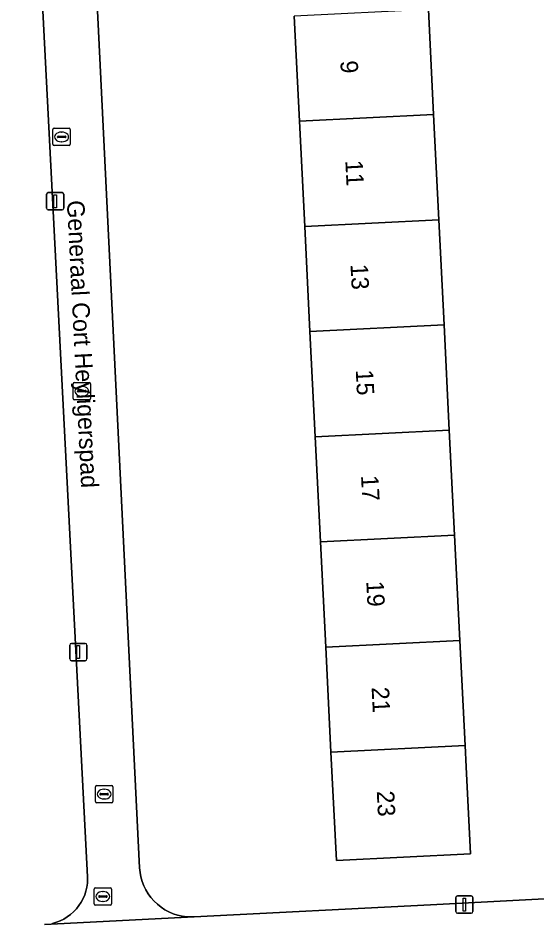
# Model space of a CAD drawing. Extents: x 161084 to 161928, y 385354 to 386522.
# Drawn here: x 161421.8 to 161451.7, y 385657.1 to 385709.2 of the extents above; entities that cross this region are included whole.
import ezdxf

# ---------------------------------------------------------------- set-up
doc = ezdxf.new("R2010")
doc.units = 0
for name, color, linetype in [('IMGEO_Erf', 7, 'Continuous'), ('IMGEO_Kolk', 7, 'Continuous'), ('IMGEO_Lichtmast', 7, 'Continuous'), ('IMGEO_Openbare_ruimte_label', 7, 'Continuous'), ('IMGEO_Pand', 7, 'Continuous'), ('IMGEO_Pand_nummerreeks', 7, 'Continuous'), ('IMGEO_Rioolput', 7, 'Continuous'), ('IMGEO_Voetpad_open', 7, 'Continuous')]:
    doc.layers.add(name, color=color, linetype=linetype)

msp = doc.modelspace()

# ---------------------------------------------------------------- linework, layer by layer
at = {"layer": 'IMGEO_Erf'}
for points in [[(161425.778, 385659.205), (161425.809, 385659.438), (161425.819, 385659.672), (161425.816, 385659.799), (161421.822, 385737.157)], [(161425.062, 385736.633), (161428.815, 385660.315), (161428.84, 385660.05), (161428.889, 385659.788), (161428.961, 385659.531), (161429.056, 385659.282), (161429.172, 385659.043), (161429.31, 385658.815), (161429.467, 385658.6), (161429.643, 385658.399), (161429.836, 385658.216), (161430.045, 385658.05), (161430.267, 385657.904), (161430.502, 385657.778), (161430.747, 385657.674), (161431.001, 385657.592), (161431.26, 385657.532), (161431.524, 385657.497), (161431.791, 385657.485), (161431.947, 385657.489), (161445.557, 385658.188), (161454.66, 385658.656)], [(161445.425, 385709.704), (161445.727, 385703.653), (161446.029, 385697.602), (161446.331, 385691.55), (161446.632, 385685.499), (161446.934, 385679.447), (161447.236, 385673.396), (161447.538, 385667.344), (161447.599, 385666.114), (161447.848, 385661.12), (161440.133, 385660.736), (161439.823, 385666.96), (161439.521, 385673.012), (161439.219, 385679.063), (161438.917, 385685.115), (161438.616, 385691.166), (161438.314, 385697.218), (161438.012, 385703.269), (161437.711, 385709.32)], [(161423.797, 385657.118), (161424.022, 385657.181), (161424.241, 385657.265), (161424.452, 385657.367), (161424.652, 385657.488), (161424.841, 385657.627), (161425.017, 385657.782), (161425.178, 385657.952), (161425.324, 385658.136), (161425.452, 385658.331), (161425.563, 385658.538), (161425.654, 385658.754), (161425.726, 385658.977), (161425.778, 385659.205)]]:
    msp.add_lwpolyline(points, dxfattribs=at)
at = {"layer": 'IMGEO_Kolk'}
for p, q in [((161425.06, 385688.232), (161425.912, 385688.232)), ((161424.985, 385687.306), (161424.985, 385688.158)), ((161425.244, 385687.726), (161425.244, 385687.738)), ((161425.682, 385687.689), (161425.284, 385687.689)), ((161425.287, 385687.775), (161425.685, 385687.775)), ((161425.473, 385688.012), (161425.498, 385688.012)), ((161425.728, 385687.738), (161425.728, 385687.726)), ((161425.986, 385688.158), (161425.986, 385687.306)), ((161425.912, 385687.232), (161425.06, 385687.232)), ((161425.496, 385687.452), (161425.471, 385687.452)), ((161426.271, 385664.126), (161426.271, 385664.978)), ((161426.346, 385665.052), (161427.198, 385665.052)), ((161426.759, 385664.832), (161426.784, 385664.832)), ((161427.272, 385664.978), (161427.272, 385664.126)), ((161426.53, 385664.546), (161426.53, 385664.558)), ((161426.968, 385664.509), (161426.57, 385664.509)), ((161426.573, 385664.595), (161426.971, 385664.595)), ((161426.782, 385664.272), (161426.757, 385664.272)), ((161427.014, 385664.558), (161427.014, 385664.546)), ((161427.198, 385664.052), (161426.346, 385664.052))]:
    msp.add_line(p, q, dxfattribs=at)
for points in [[(161425.06, 385688.232), (161425.912, 385688.232)], [(161424.985, 385687.306), (161424.985, 385688.158)], [(161425.986, 385688.158), (161425.986, 385687.306)], [(161425.912, 385687.232), (161425.06, 385687.232)], [(161426.271, 385664.126), (161426.271, 385664.978)], [(161426.346, 385665.052), (161427.198, 385665.052)], [(161427.272, 385664.978), (161427.272, 385664.126)], [(161427.198, 385664.052), (161426.346, 385664.052)]]:
    msp.add_lwpolyline(points, dxfattribs=at)
for centre, radius, start, end in [((161425.062, 385688.156), 0.0765, 91.552, 178.448), ((161425.062, 385688.156), 0.0765, 91.552, 178.448), ((161425.91, 385688.156), 0.0765, 1.552, 88.448), ((161425.91, 385688.156), 0.0765, 1.552, 88.448), ((161425.284, 385687.735), 0.0403, 85.8775, 175.7526), ((161425.281, 385687.725), 0.0366, 178.938, 274.7102), ((161425.685, 385687.732), 0.043, 264.8664, 352.4533), ((161425.689, 385687.737), 0.0386, 1.7309, 96.639), ((161425.062, 385687.308), 0.0765, 181.552, 268.448), ((161425.062, 385687.308), 0.0765, 181.552, 268.448), ((161425.91, 385687.308), 0.0765, 271.552, 358.448), ((161425.91, 385687.308), 0.0765, 271.552, 358.448), ((161426.348, 385664.976), 0.0765, 91.552, 178.448), ((161426.348, 385664.976), 0.0765, 91.552, 178.448), ((161427.196, 385664.976), 0.0765, 1.552, 88.448), ((161427.196, 385664.976), 0.0765, 1.552, 88.448), ((161426.57, 385664.555), 0.0403, 85.8775, 175.7526), ((161426.567, 385664.545), 0.0366, 178.938, 274.7102), ((161426.971, 385664.552), 0.043, 264.8664, 352.4533), ((161426.975, 385664.557), 0.0386, 1.7309, 96.639), ((161426.348, 385664.128), 0.0765, 181.552, 268.448), ((161426.348, 385664.128), 0.0765, 181.552, 268.448), ((161427.196, 385664.128), 0.0765, 271.552, 358.448), ((161427.196, 385664.128), 0.0765, 271.552, 358.448)]:
    msp.add_arc(centre, radius, start, end, dxfattribs=at)
for centre, major_axis, ratio, start_param, end_param in [((161425.472, 385687.732), (-0.387, 0.002), 0.722429, 4.712389, 7.853982), ((161425.497, 385687.732), (-0.39, 0.002), 0.717154, 1.570796, 4.712389), ((161426.758, 385664.552), (-0.387, 0.002), 0.722429, 4.712389, 7.853982), ((161426.783, 385664.552), (-0.39, 0.002), 0.717154, 1.570796, 4.712389)]:
    msp.add_ellipse(centre, major_axis=major_axis, ratio=ratio, start_param=start_param, end_param=end_param, dxfattribs=at)
at = {"layer": 'IMGEO_Lichtmast'}
for p, q in [((161423.559, 385699.164), (161424.349, 385699.164)), ((161424.349, 385699.164), (161423.559, 385699.164)), ((161423.459, 385698.264), (161423.459, 385699.064)), ((161423.459, 385699.064), (161423.459, 385698.264)), ((161424.449, 385699.064), (161424.449, 385698.264)), ((161424.449, 385698.264), (161424.449, 385699.064)), ((161424.349, 385698.164), (161423.559, 385698.164)), ((161423.559, 385698.164), (161424.349, 385698.164)), ((161424.789, 385672.327), (161424.789, 385673.127)), ((161424.789, 385673.127), (161424.789, 385672.327)), ((161424.889, 385673.227), (161425.679, 385673.227)), ((161425.679, 385673.227), (161424.889, 385673.227)), ((161425.779, 385673.127), (161425.779, 385672.327)), ((161425.779, 385672.327), (161425.779, 385673.127)), ((161425.679, 385672.227), (161424.889, 385672.227)), ((161424.889, 385672.227), (161425.679, 385672.227)), ((161447, 385657.799), (161447, 385658.599)), ((161447, 385658.599), (161447, 385657.799)), ((161447.1, 385658.699), (161447.89, 385658.699)), ((161447.89, 385658.699), (161447.1, 385658.699)), ((161447.99, 385658.599), (161447.99, 385657.799)), ((161447.99, 385657.799), (161447.99, 385658.599)), ((161447.89, 385657.699), (161447.1, 385657.699)), ((161447.1, 385657.699), (161447.89, 385657.699))]:
    msp.add_line(p, q, dxfattribs=at)
for points in [[(161423.879, 385699.039), (161424.029, 385699.039), (161424.029, 385698.289), (161423.879, 385698.289), (161423.879, 385699.039)], [(161425.209, 385673.102), (161425.359, 385673.102), (161425.359, 385672.352), (161425.209, 385672.352), (161425.209, 385673.102)], [(161447.42, 385658.574), (161447.57, 385658.574), (161447.57, 385657.824), (161447.42, 385657.824), (161447.42, 385658.574)]]:
    msp.add_lwpolyline(points, dxfattribs=at)
for centre, start, end in [((161423.559, 385699.064), 90, 180), ((161423.559, 385699.064), 90, 180), ((161424.349, 385699.064), 0, 90), ((161424.349, 385699.064), 360, 90), ((161423.559, 385698.264), 180, 270), ((161423.559, 385698.264), 180, 270), ((161424.349, 385698.264), 270, 0), ((161424.349, 385698.264), 270, 0), ((161424.889, 385673.127), 90, 180), ((161424.889, 385673.127), 90, 180), ((161425.679, 385673.127), 0, 90), ((161425.679, 385673.127), 360, 90), ((161424.889, 385672.327), 180, 270), ((161424.889, 385672.327), 180, 270), ((161425.679, 385672.327), 270, 0), ((161425.679, 385672.327), 270, 0), ((161447.1, 385658.599), 90, 180), ((161447.1, 385658.599), 90, 180), ((161447.89, 385658.599), 0, 90), ((161447.89, 385658.599), 360, 90), ((161447.1, 385657.799), 180, 270), ((161447.1, 385657.799), 180, 270), ((161447.89, 385657.799), 270, 0), ((161447.89, 385657.799), 270, 0)]:
    msp.add_arc(centre, 0.1, start, end, dxfattribs=at)
at = {"layer": 'IMGEO_Pand'}
for points in [[(161445.727, 385703.653), (161445.425, 385709.704), (161437.711, 385709.32), (161438.012, 385703.269)], [(161438.012, 385703.269), (161438.314, 385697.218), (161446.029, 385697.602), (161445.727, 385703.653)], [(161446.331, 385691.55), (161446.029, 385697.602), (161438.314, 385697.218), (161438.616, 385691.166)], [(161438.616, 385691.166), (161438.917, 385685.115), (161446.632, 385685.499), (161446.331, 385691.55)], [(161446.934, 385679.447), (161446.632, 385685.499), (161438.917, 385685.115), (161439.219, 385679.063)], [(161447.236, 385673.396), (161446.934, 385679.447), (161439.219, 385679.063), (161439.521, 385673.012)], [(161447.538, 385667.344), (161447.236, 385673.396), (161439.521, 385673.012), (161439.823, 385666.96)], [(161439.823, 385666.96), (161440.133, 385660.736), (161447.848, 385661.12), (161447.599, 385666.114), (161447.538, 385667.344)]]:
    msp.add_lwpolyline(points, close=True, dxfattribs=at)
at = {"layer": 'IMGEO_Rioolput'}
for p, q in [((161423.825, 385701.939), (161423.825, 385702.791)), ((161423.9, 385702.865), (161424.752, 385702.865)), ((161424.826, 385702.791), (161424.826, 385701.939)), ((161424.084, 385702.359), (161424.084, 385702.371)), ((161424.522, 385702.322), (161424.124, 385702.322)), ((161424.127, 385702.408), (161424.525, 385702.408)), ((161424.313, 385702.645), (161424.338, 385702.645)), ((161424.568, 385702.371), (161424.568, 385702.359)), ((161424.752, 385701.865), (161423.9, 385701.865)), ((161424.336, 385702.085), (161424.311, 385702.085)), ((161426.199, 385658.236), (161426.199, 385659.088)), ((161426.274, 385659.162), (161427.126, 385659.162)), ((161427.2, 385659.088), (161427.2, 385658.236)), ((161426.458, 385658.656), (161426.458, 385658.668)), ((161426.896, 385658.619), (161426.498, 385658.619)), ((161426.501, 385658.705), (161426.899, 385658.705)), ((161426.687, 385658.942), (161426.712, 385658.942)), ((161426.942, 385658.668), (161426.942, 385658.656)), ((161427.126, 385658.162), (161426.274, 385658.162)), ((161426.71, 385658.382), (161426.685, 385658.382))]:
    msp.add_line(p, q, dxfattribs=at)
for points in [[(161423.825, 385701.939), (161423.825, 385702.791)], [(161423.9, 385702.865), (161424.752, 385702.865)], [(161424.826, 385702.791), (161424.826, 385701.939)], [(161424.752, 385701.865), (161423.9, 385701.865)], [(161426.199, 385658.236), (161426.199, 385659.088)], [(161426.274, 385659.162), (161427.126, 385659.162)], [(161427.2, 385659.088), (161427.2, 385658.236)], [(161427.126, 385658.162), (161426.274, 385658.162)]]:
    msp.add_lwpolyline(points, dxfattribs=at)
for centre, radius, start, end in [((161423.902, 385702.789), 0.0765, 91.552, 178.448), ((161423.902, 385702.789), 0.0765, 91.552, 178.448), ((161424.75, 385702.789), 0.0765, 1.552, 88.448), ((161424.75, 385702.789), 0.0765, 1.552, 88.448), ((161424.124, 385702.368), 0.0403, 85.8775, 175.7526), ((161424.121, 385702.358), 0.0366, 178.938, 274.7102), ((161424.525, 385702.365), 0.043, 264.8664, 352.4533), ((161424.529, 385702.37), 0.0386, 1.7309, 96.639), ((161423.902, 385701.941), 0.0765, 181.552, 268.448), ((161423.902, 385701.941), 0.0765, 181.552, 268.448), ((161424.75, 385701.941), 0.0765, 271.552, 358.448), ((161424.75, 385701.941), 0.0765, 271.552, 358.448), ((161426.276, 385659.086), 0.0765, 91.552, 178.448), ((161426.276, 385659.086), 0.0765, 91.552, 178.448), ((161427.124, 385659.086), 0.0765, 1.552, 88.448), ((161427.124, 385659.086), 0.0765, 1.552, 88.448), ((161426.498, 385658.665), 0.0403, 85.8775, 175.7526), ((161426.495, 385658.655), 0.0366, 178.938, 274.7102), ((161426.899, 385658.662), 0.043, 264.8664, 352.4533), ((161426.903, 385658.667), 0.0386, 1.7309, 96.639), ((161426.276, 385658.238), 0.0765, 181.552, 268.448), ((161426.276, 385658.238), 0.0765, 181.552, 268.448), ((161427.124, 385658.238), 0.0765, 271.552, 358.448), ((161427.124, 385658.238), 0.0765, 271.552, 358.448)]:
    msp.add_arc(centre, radius, start, end, dxfattribs=at)
for centre, major_axis, ratio, start_param, end_param in [((161424.312, 385702.365), (-0.387, 0.002), 0.722429, 4.712389, 7.853982), ((161424.337, 385702.365), (-0.39, 0.002), 0.717154, 1.570796, 4.712389), ((161426.686, 385658.662), (-0.387, 0.002), 0.722429, 4.712389, 7.853982), ((161426.711, 385658.662), (-0.39, 0.002), 0.717154, 1.570796, 4.712389)]:
    msp.add_ellipse(centre, major_axis=major_axis, ratio=ratio, start_param=start_param, end_param=end_param, dxfattribs=at)
at = {"layer": 'IMGEO_Voetpad_open'}
for points in [[(161421.822, 385737.157), (161425.816, 385659.799), (161425.819, 385659.672), (161425.809, 385659.438), (161425.778, 385659.205), (161425.726, 385658.977), (161425.654, 385658.754), (161425.563, 385658.538), (161425.452, 385658.331), (161425.324, 385658.136), (161425.178, 385657.952), (161425.017, 385657.782), (161424.841, 385657.627), (161424.652, 385657.488), (161424.452, 385657.367), (161424.241, 385657.265), (161424.022, 385657.181), (161423.797, 385657.118)], [(161423.333, 385657.052), (161431.947, 385657.489), (161431.791, 385657.485), (161431.524, 385657.497), (161431.26, 385657.532), (161431.001, 385657.592), (161430.747, 385657.674), (161430.502, 385657.778), (161430.267, 385657.904), (161430.045, 385658.05), (161429.836, 385658.216), (161429.643, 385658.399), (161429.467, 385658.6), (161429.31, 385658.815), (161429.172, 385659.043), (161429.056, 385659.282), (161428.961, 385659.531), (161428.889, 385659.788), (161428.84, 385660.05), (161428.815, 385660.315), (161425.062, 385736.633)], [(161457.001, 385657.103), (161457.453, 385657.375), (161457.026, 385661.142), (161457.016, 385660.919), (161456.986, 385660.699), (161456.937, 385660.482), (161456.868, 385660.27), (161456.781, 385660.065), (161456.676, 385659.869), (161456.553, 385659.683), (161456.415, 385659.508), (161456.261, 385659.347), (161456.094, 385659.2), (161455.914, 385659.069), (161455.723, 385658.954), (161455.523, 385658.857), (161455.315, 385658.778), (161455.101, 385658.718), (161454.882, 385658.677), (161454.66, 385658.656), (161445.557, 385658.188), (161431.947, 385657.489), (161423.333, 385657.052)]]:
    msp.add_lwpolyline(points, dxfattribs=at)

# ---------------------------------------------------------------- texts
at = {"layer": 'IMGEO_Openbare_ruimte_label'}
msp.add_text('Generaal Cort Heyligerspad', height=1, rotation=272.8653, dxfattribs=at).set_placement((161424.629, 385698.697))
at = {"layer": 'IMGEO_Pand_nummerreeks'}
for s, p in [('9', (161440.362, 385706.738)), ('11', (161440.648, 385701.004)), ('13', (161440.945, 385695.037)), ('15', (161441.248, 385688.957)), ('17', (161441.551, 385682.877)), ('19', (161441.854, 385676.797)), ('21', (161442.16, 385670.695)), ('23', (161442.457, 385664.727))]:
    msp.add_text(s, height=1, rotation=272.8545, dxfattribs=at).set_placement(p)

doc.saveas('drawing.dxf')
